// Mitsubishi GX Works2 project: FX3G_COM3_ADPRW   PLC: FX3G

PROGRAM MAIN
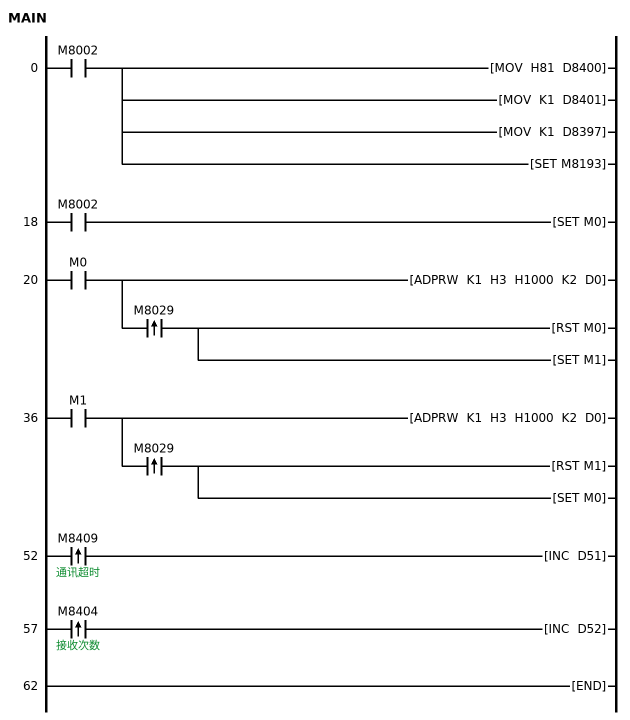
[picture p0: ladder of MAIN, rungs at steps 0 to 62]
0     LD      M8002
      MOV     H81 D8400
        [note] 通讯设定9600 8 N 1
      MOV     K1 D8401
        [note] modbus主站
      MOV     K1 D8397
        [note] 串口3切换
      SET     M8193
        [note] on:其他协议协议off:编程口协议
18    LD      M8002
      SET     M0
20    LD      M0
      ADPRW   K1 H3 H1000 K2 D0
      ANDP    M8029
      RST     M0
      SET     M1
36    LD      M1
      ADPRW   K1 H3 H1000 K2 D0
      ANDP    M8029
      RST     M1
      SET     M0
52    LDP     M8409  ; 通讯超时
      INC     D51
57    LDP     M8404  ; 接收次数
      INC     D52
62    END
END_PROGRAM

// device comments not shown above
D200  ; 写入数量，1个
D211  ; 转速
M2  ; 反转
M3  ; 停止
